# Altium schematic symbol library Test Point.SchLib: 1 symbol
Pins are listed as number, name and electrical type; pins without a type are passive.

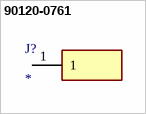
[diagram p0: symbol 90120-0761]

## 90120-0761
designator J?
Connector; Manufacturer_Name: Molex; Manufacturer_Part_Number: 90120-0761
footprint HDRV1W90P0X254_1X1_232X249X560P
pins: 1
